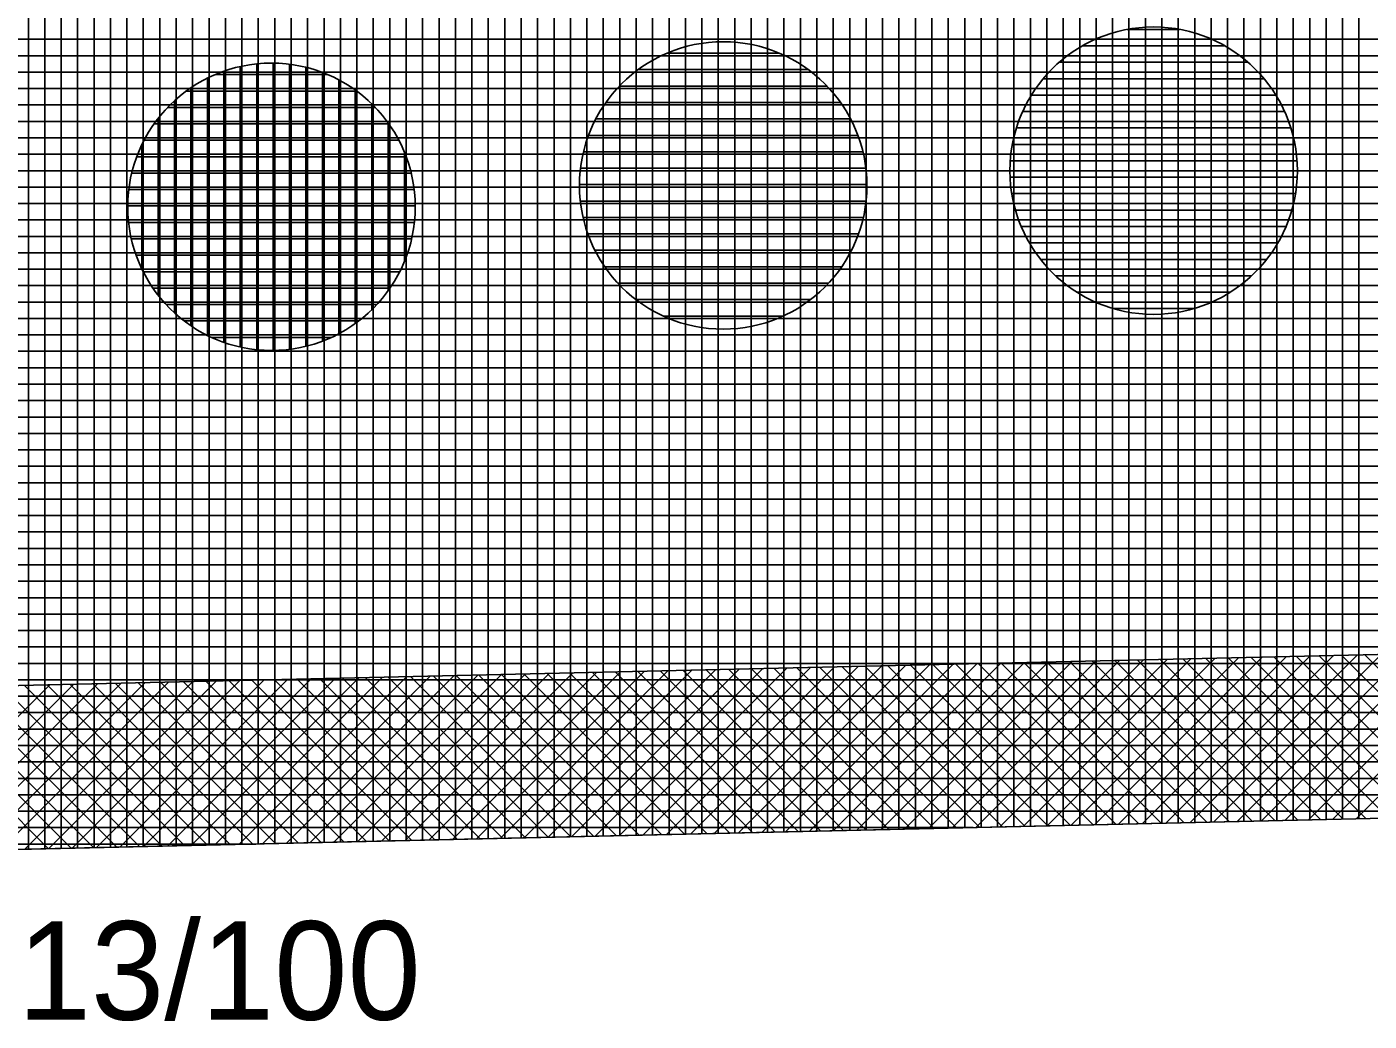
# Model space of a CAD drawing. Extents: x -565346 to -564154, y -1097386 to -1095620.
# Drawn here: x -565257.74 to -565241.4, y -1095873.9 to -1095861.79 of the extents above; entities that cross this region are included whole.
import ezdxf

# ---------------------------------------------------------------- set-up
doc = ezdxf.new("R2010")
doc.units = 0
for name, color, linetype in [('Vrstva 1', 7, 'Continuous'), ('Vrstva 40', 7, 'Continuous'), ('Vrstva 41', 7, 'Continuous'), ('Vrstva 42', 7, 'Continuous'), ('Vrstva 43', 7, 'Continuous'), ('Vrstva 44', 7, 'Continuous')]:
    doc.layers.add(name, color=color, linetype=linetype)

msp = doc.modelspace()

# ---------------------------------------------------------------- linework, layer by layer
at = {"layer": 'Vrstva 1'}
msp.add_line((-565318.28, -1095873.19), (-565230.93, -1095871.19), dxfattribs=at)
at = {"layer": 'Vrstva 41'}
for p, q in [((-565244.723, -1095869.512), (-565246.764, -1095871.553)), ((-565244.434, -1095869.505), (-565246.475, -1095871.546)), ((-565244.145, -1095869.498), (-565246.185, -1095871.539)), ((-565243.855, -1095869.492), (-565245.896, -1095871.533)), ((-565243.566, -1095869.485), (-565245.607, -1095871.526)), ((-565243.276, -1095869.479), (-565245.317, -1095871.519)), ((-565242.987, -1095869.472), (-565245.028, -1095871.513)), ((-565242.819, -1095871.462), (-565244.768, -1095869.513)), ((-565242.697, -1095869.465), (-565244.738, -1095871.506)), ((-565242.542, -1095871.456), (-565244.492, -1095869.506)), ((-565242.408, -1095869.459), (-565244.449, -1095871.5)), ((-565242.266, -1095871.45), (-565244.215, -1095869.5)), ((-565242.118, -1095869.452), (-565244.159, -1095871.493)), ((-565241.989, -1095871.443), (-565243.939, -1095869.494)), ((-565241.829, -1095869.446), (-565243.87, -1095871.486)), ((-565241.713, -1095871.437), (-565243.662, -1095869.487)), ((-565241.54, -1095869.439), (-565243.58, -1095871.48)), ((-565241.436, -1095871.431), (-565243.386, -1095869.481)), ((-565241.25, -1095869.432), (-565243.291, -1095871.473)), ((-565241.16, -1095871.424), (-565243.109, -1095869.475)), ((-565240.961, -1095869.426), (-565243.001, -1095871.466)), ((-565240.883, -1095871.418), (-565242.833, -1095869.469)), ((-565240.671, -1095869.419), (-565242.712, -1095871.46)), ((-565240.607, -1095871.412), (-565242.556, -1095869.462)), ((-565240.382, -1095869.413), (-565242.422, -1095871.453)), ((-565240.33, -1095871.405), (-565242.28, -1095869.456)), ((-565240.092, -1095869.406), (-565242.133, -1095871.447)), ((-565240.054, -1095871.399), (-565242.003, -1095869.45)), ((-565239.803, -1095869.399), (-565241.843, -1095871.44)), ((-565239.777, -1095871.393), (-565241.727, -1095869.443)), ((-565239.513, -1095869.393), (-565241.554, -1095871.433)), ((-565239.501, -1095871.386), (-565241.45, -1095869.437)), ((-565251.96, -1095869.677), (-565254.001, -1095871.718)), ((-565251.67, -1095869.67), (-565253.712, -1095871.712)), ((-565251.381, -1095869.664), (-565253.422, -1095871.705)), ((-565251.091, -1095869.657), (-565253.133, -1095871.698)), ((-565250.802, -1095869.65), (-565252.843, -1095871.692)), ((-565250.512, -1095869.644), (-565252.554, -1095871.685)), ((-565250.223, -1095869.637), (-565252.264, -1095871.678)), ((-565249.934, -1095869.631), (-565251.975, -1095871.672)), ((-565250.008, -1095871.627), (-565251.958, -1095869.677)), ((-565249.644, -1095869.624), (-565251.685, -1095871.665)), ((-565249.732, -1095871.62), (-565251.682, -1095869.67)), ((-565249.455, -1095871.614), (-565251.405, -1095869.664)), ((-565249.355, -1095869.617), (-565251.396, -1095871.659)), ((-565249.179, -1095871.608), (-565251.129, -1095869.658)), ((-565249.065, -1095869.611), (-565251.106, -1095871.652)), ((-565248.902, -1095871.601), (-565250.852, -1095869.651)), ((-565248.776, -1095869.604), (-565250.817, -1095871.645)), ((-565248.626, -1095871.595), (-565250.576, -1095869.645)), ((-565248.486, -1095869.598), (-565250.528, -1095871.639)), ((-565248.349, -1095871.589), (-565250.299, -1095869.639)), ((-565248.197, -1095869.591), (-565250.238, -1095871.632)), ((-565248.073, -1095871.583), (-565250.023, -1095869.633)), ((-565247.907, -1095869.584), (-565249.949, -1095871.625)), ((-565247.796, -1095871.576), (-565249.746, -1095869.626)), ((-565247.618, -1095869.578), (-565249.659, -1095871.619)), ((-565247.52, -1095871.57), (-565249.469, -1095869.62)), ((-565247.329, -1095869.571), (-565249.37, -1095871.612)), ((-565247.243, -1095871.564), (-565249.193, -1095869.614)), ((-565247.039, -1095869.564), (-565249.08, -1095871.606)), ((-565246.967, -1095871.557), (-565248.916, -1095869.607)), ((-565246.75, -1095869.558), (-565248.791, -1095871.599)), ((-565246.69, -1095871.551), (-565248.64, -1095869.601)), ((-565246.46, -1095869.551), (-565248.501, -1095871.592)), ((-565246.414, -1095871.545), (-565248.363, -1095869.595)), ((-565246.171, -1095869.545), (-565248.212, -1095871.586)), ((-565246.137, -1095871.538), (-565248.087, -1095869.588)), ((-565245.881, -1095869.538), (-565247.922, -1095871.579)), ((-565245.86, -1095871.532), (-565247.81, -1095869.582)), ((-565245.592, -1095869.531), (-565247.633, -1095871.572)), ((-565245.584, -1095871.526), (-565247.534, -1095869.576)), ((-565245.302, -1095869.525), (-565247.343, -1095871.566)), ((-565245.307, -1095871.519), (-565247.257, -1095869.569)), ((-565245.013, -1095869.518), (-565247.054, -1095871.559)), ((-565245.031, -1095871.513), (-565246.981, -1095869.563)), ((-565244.754, -1095871.507), (-565246.704, -1095869.557)), ((-565244.478, -1095871.5), (-565246.428, -1095869.551)), ((-565244.201, -1095871.494), (-565246.151, -1095869.544)), ((-565243.925, -1095871.488), (-565245.875, -1095869.538)), ((-565243.648, -1095871.481), (-565245.598, -1095869.532)), ((-565243.372, -1095871.475), (-565245.321, -1095869.525)), ((-565243.095, -1095871.469), (-565245.045, -1095869.519)), ((-565257.459, -1095869.802), (-565259.501, -1095871.844)), ((-565257.17, -1095869.796), (-565259.212, -1095871.838)), ((-565257.197, -1095871.791), (-565259.148, -1095869.841)), ((-565256.88, -1095869.789), (-565258.922, -1095871.831)), ((-565256.921, -1095871.785), (-565258.872, -1095869.834)), ((-565256.591, -1095869.782), (-565258.633, -1095871.824)), ((-565256.644, -1095871.779), (-565258.595, -1095869.828)), ((-565256.301, -1095869.776), (-565258.343, -1095871.818)), ((-565256.368, -1095871.772), (-565258.319, -1095869.822)), ((-565256.012, -1095869.769), (-565258.054, -1095871.811)), ((-565256.091, -1095871.766), (-565258.042, -1095869.816)), ((-565255.815, -1095871.76), (-565257.765, -1095869.809)), ((-565255.722, -1095869.763), (-565257.764, -1095871.804)), ((-565255.538, -1095871.753), (-565257.489, -1095869.803)), ((-565255.433, -1095869.756), (-565257.475, -1095871.798)), ((-565255.262, -1095871.747), (-565257.212, -1095869.797)), ((-565255.144, -1095869.749), (-565257.185, -1095871.791)), ((-565254.985, -1095871.741), (-565256.936, -1095869.79)), ((-565254.854, -1095869.743), (-565256.896, -1095871.785)), ((-565254.709, -1095871.734), (-565256.659, -1095869.784)), ((-565254.565, -1095869.736), (-565256.606, -1095871.778)), ((-565254.432, -1095871.728), (-565256.383, -1095869.778)), ((-565254.275, -1095869.73), (-565256.317, -1095871.771)), ((-565254.156, -1095871.722), (-565256.106, -1095869.771)), ((-565253.986, -1095869.723), (-565256.027, -1095871.765)), ((-565253.879, -1095871.715), (-565255.83, -1095869.765)), ((-565253.696, -1095869.716), (-565255.738, -1095871.758)), ((-565253.603, -1095871.709), (-565255.553, -1095869.759)), ((-565253.407, -1095869.71), (-565255.449, -1095871.751)), ((-565253.326, -1095871.703), (-565255.277, -1095869.752)), ((-565253.117, -1095869.703), (-565255.159, -1095871.745)), ((-565253.05, -1095871.696), (-565255, -1095869.746)), ((-565252.828, -1095869.697), (-565254.87, -1095871.738)), ((-565252.773, -1095871.69), (-565254.724, -1095869.74)), ((-565252.539, -1095869.69), (-565254.58, -1095871.732)), ((-565252.497, -1095871.684), (-565254.447, -1095869.734)), ((-565252.249, -1095869.683), (-565254.291, -1095871.725)), ((-565252.22, -1095871.677), (-565254.171, -1095869.727)), ((-565251.944, -1095871.671), (-565253.894, -1095869.721)), ((-565251.667, -1095871.665), (-565253.617, -1095869.715)), ((-565251.391, -1095871.658), (-565253.341, -1095869.708)), ((-565251.114, -1095871.652), (-565253.064, -1095869.702)), ((-565250.838, -1095871.646), (-565252.788, -1095869.696)), ((-565250.561, -1095871.639), (-565252.511, -1095869.689)), ((-565250.285, -1095871.633), (-565252.235, -1095869.683)), ((-565257.474, -1095871.798), (-565259.425, -1095869.847))]:
    msp.add_line(p, q, dxfattribs=at)
at = {"layer": 'Vrstva 42'}
msp.add_lwpolyline([(-565179.232, -1095865.407), (-565179.369, -1095863.41), (-565231.152, -1095869.202), (-565318.326, -1095871.191), (-565322.325, -1095871.281), (-565322.28, -1095873.28), (-565318.28, -1095873.19), (-565230.93, -1095871.19)], close=True, dxfattribs=at)
at = {"layer": 'Vrstva 43'}
for p, q in [((-565242.12, -1095856.439), (-565242.12, -1095871.446)), ((-565241.92, -1095856.435), (-565241.92, -1095871.442)), ((-565241.72, -1095856.43), (-565241.72, -1095871.437)), ((-565241.52, -1095856.425), (-565241.52, -1095871.432)), ((-565249.32, -1095856.605), (-565249.32, -1095871.611)), ((-565249.12, -1095856.6), (-565249.12, -1095871.606)), ((-565248.92, -1095856.595), (-565248.92, -1095871.602)), ((-565248.72, -1095856.591), (-565248.72, -1095871.597)), ((-565248.52, -1095856.586), (-565248.52, -1095871.593)), ((-565248.32, -1095856.582), (-565248.32, -1095871.588)), ((-565248.12, -1095856.577), (-565248.12, -1095871.584)), ((-565247.92, -1095856.572), (-565247.92, -1095871.579)), ((-565247.72, -1095856.568), (-565247.72, -1095871.574)), ((-565247.52, -1095856.563), (-565247.52, -1095871.57)), ((-565247.32, -1095856.559), (-565247.32, -1095871.565)), ((-565247.12, -1095856.554), (-565247.12, -1095871.561)), ((-565246.92, -1095856.549), (-565246.92, -1095871.556)), ((-565246.72, -1095856.545), (-565246.72, -1095871.552)), ((-565246.52, -1095856.54), (-565246.52, -1095871.547)), ((-565246.32, -1095856.536), (-565246.32, -1095871.542)), ((-565246.12, -1095856.531), (-565246.12, -1095871.538)), ((-565245.92, -1095856.526), (-565245.92, -1095871.533)), ((-565245.72, -1095856.522), (-565245.72, -1095871.529)), ((-565245.52, -1095856.517), (-565245.52, -1095871.524)), ((-565245.32, -1095856.513), (-565245.32, -1095871.519)), ((-565245.12, -1095856.508), (-565245.12, -1095871.515)), ((-565244.92, -1095856.503), (-565244.92, -1095871.51)), ((-565244.72, -1095856.499), (-565244.72, -1095871.506)), ((-565244.52, -1095856.494), (-565244.52, -1095871.501)), ((-565244.32, -1095856.49), (-565244.32, -1095871.497)), ((-565244.12, -1095856.485), (-565244.12, -1095871.492)), ((-565243.92, -1095856.481), (-565243.92, -1095871.487)), ((-565243.72, -1095856.476), (-565243.72, -1095871.483)), ((-565243.52, -1095856.471), (-565243.52, -1095871.478)), ((-565243.32, -1095856.467), (-565243.32, -1095871.474)), ((-565243.12, -1095856.462), (-565243.12, -1095871.469)), ((-565242.92, -1095856.458), (-565242.92, -1095871.465)), ((-565242.72, -1095856.453), (-565242.72, -1095871.46)), ((-565242.52, -1095856.448), (-565242.52, -1095871.455)), ((-565242.32, -1095856.444), (-565242.32, -1095871.451)), ((-565256.32, -1095856.765), (-565256.32, -1095871.771)), ((-565256.12, -1095856.761), (-565256.12, -1095871.767)), ((-565255.92, -1095856.756), (-565255.92, -1095871.762)), ((-565255.72, -1095856.752), (-565255.72, -1095871.758)), ((-565255.52, -1095856.747), (-565255.52, -1095871.753)), ((-565255.32, -1095856.742), (-565255.32, -1095871.748)), ((-565255.12, -1095856.738), (-565255.12, -1095871.744)), ((-565254.92, -1095856.733), (-565254.92, -1095871.739)), ((-565254.72, -1095856.729), (-565254.72, -1095871.735)), ((-565254.52, -1095856.724), (-565254.52, -1095871.73)), ((-565254.32, -1095856.719), (-565254.32, -1095871.726)), ((-565254.12, -1095856.715), (-565254.12, -1095871.721)), ((-565253.92, -1095856.71), (-565253.92, -1095871.716)), ((-565253.72, -1095856.706), (-565253.72, -1095871.712)), ((-565253.52, -1095856.701), (-565253.52, -1095871.707)), ((-565253.32, -1095856.696), (-565253.32, -1095871.703)), ((-565253.12, -1095856.692), (-565253.12, -1095871.698)), ((-565252.92, -1095856.687), (-565252.92, -1095871.693)), ((-565252.72, -1095856.683), (-565252.72, -1095871.689)), ((-565252.52, -1095856.678), (-565252.52, -1095871.684)), ((-565252.32, -1095856.673), (-565252.32, -1095871.68)), ((-565252.12, -1095856.669), (-565252.12, -1095871.675)), ((-565251.92, -1095856.664), (-565251.92, -1095871.671)), ((-565251.72, -1095856.66), (-565251.72, -1095871.666)), ((-565251.52, -1095856.655), (-565251.52, -1095871.661)), ((-565251.32, -1095856.65), (-565251.32, -1095871.657)), ((-565251.12, -1095856.646), (-565251.12, -1095871.652)), ((-565250.92, -1095856.641), (-565250.92, -1095871.648)), ((-565250.72, -1095856.637), (-565250.72, -1095871.643)), ((-565250.52, -1095856.632), (-565250.52, -1095871.639)), ((-565250.32, -1095856.628), (-565250.32, -1095871.634)), ((-565250.12, -1095856.623), (-565250.12, -1095871.629)), ((-565249.92, -1095856.618), (-565249.92, -1095871.625)), ((-565249.72, -1095856.614), (-565249.72, -1095871.62)), ((-565249.52, -1095856.609), (-565249.52, -1095871.616)), ((-565257.72, -1095856.797), (-565257.72, -1095871.803)), ((-565257.52, -1095856.793), (-565257.52, -1095871.799)), ((-565257.32, -1095856.788), (-565257.32, -1095871.794)), ((-565257.12, -1095856.784), (-565257.12, -1095871.79)), ((-565256.92, -1095856.779), (-565256.92, -1095871.785)), ((-565256.72, -1095856.775), (-565256.72, -1095871.78)), ((-565256.52, -1095856.77), (-565256.52, -1095871.776)), ((-565148.233, -1095861.94), (-565322.505, -1095861.94)), ((-565150.021, -1095862.14), (-565322.501, -1095862.14)), ((-565151.809, -1095862.34), (-565322.497, -1095862.34)), ((-565153.597, -1095862.54), (-565322.493, -1095862.54)), ((-565155.385, -1095862.74), (-565322.489, -1095862.74)), ((-565157.173, -1095862.94), (-565322.485, -1095862.94)), ((-565158.961, -1095863.14), (-565322.481, -1095863.14)), ((-565160.749, -1095863.34), (-565322.477, -1095863.34)), ((-565162.537, -1095863.54), (-565322.473, -1095863.54)), ((-565164.325, -1095863.74), (-565322.469, -1095863.74)), ((-565166.113, -1095863.94), (-565322.465, -1095863.94)), ((-565167.901, -1095864.14), (-565322.461, -1095864.14)), ((-565169.689, -1095864.34), (-565322.457, -1095864.34)), ((-565171.477, -1095864.54), (-565322.453, -1095864.54)), ((-565173.265, -1095864.74), (-565322.449, -1095864.74)), ((-565175.053, -1095864.94), (-565322.445, -1095864.94)), ((-565176.841, -1095865.14), (-565322.441, -1095865.14)), ((-565178.629, -1095865.34), (-565322.437, -1095865.34)), ((-565180.418, -1095865.54), (-565322.433, -1095865.54)), ((-565182.206, -1095865.74), (-565322.429, -1095865.74)), ((-565183.994, -1095865.94), (-565322.426, -1095865.94)), ((-565185.782, -1095866.14), (-565322.422, -1095866.14)), ((-565187.57, -1095866.34), (-565322.418, -1095866.34)), ((-565189.358, -1095866.54), (-565322.414, -1095866.54)), ((-565191.146, -1095866.74), (-565322.41, -1095866.74)), ((-565192.934, -1095866.94), (-565322.406, -1095866.94)), ((-565194.722, -1095867.14), (-565322.402, -1095867.14)), ((-565196.51, -1095867.34), (-565322.398, -1095867.34)), ((-565198.298, -1095867.54), (-565322.394, -1095867.54)), ((-565200.086, -1095867.74), (-565322.39, -1095867.74)), ((-565201.874, -1095867.94), (-565322.386, -1095867.94)), ((-565203.662, -1095868.14), (-565322.382, -1095868.14)), ((-565205.45, -1095868.34), (-565322.378, -1095868.34)), ((-565207.238, -1095868.54), (-565322.374, -1095868.54)), ((-565209.026, -1095868.74), (-565322.37, -1095868.74)), ((-565210.814, -1095868.94), (-565322.366, -1095868.94)), ((-565212.602, -1095869.14), (-565322.362, -1095869.14)), ((-565214.391, -1095869.34), (-565322.358, -1095869.34)), ((-565216.179, -1095869.54), (-565322.354, -1095869.54)), ((-565217.967, -1095869.74), (-565322.35, -1095869.74)), ((-565219.755, -1095869.94), (-565322.346, -1095869.94)), ((-565221.543, -1095870.14), (-565322.342, -1095870.14)), ((-565223.331, -1095870.34), (-565322.338, -1095870.34)), ((-565225.119, -1095870.54), (-565322.334, -1095870.54)), ((-565226.907, -1095870.74), (-565322.33, -1095870.74)), ((-565228.695, -1095870.94), (-565322.326, -1095870.94)), ((-565230.483, -1095871.14), (-565322.322, -1095871.14)), ((-565237.481, -1095871.34), (-565322.318, -1095871.34)), ((-565246.216, -1095871.54), (-565322.314, -1095871.54)), ((-565254.951, -1095871.74), (-565322.311, -1095871.74))]:
    msp.add_line(p, q, dxfattribs=at)
msp.add_lwpolyline([(-565311.82, -1095858.04), (-565322.62, -1095856.13), (-565322.28, -1095873.28), (-565318.28, -1095873.19), (-565230.93, -1095871.19), (-565052.84, -1095851.27), (-565052.77, -1095836.13), (-565130.42, -1095846.37), (-565188.3, -1095850.34), (-565231.27, -1095856.19)], close=True, dxfattribs=at)
at = {"layer": 'Vrstva 44'}
for p, q in [((-565244.34, -1095861.82), (-565243.706, -1095861.82)), ((-565244.32, -1095861.816), (-565244.32, -1095865.262)), ((-565244.12, -1095861.794), (-565244.12, -1095865.285)), ((-565243.92, -1095861.795), (-565243.92, -1095865.286)), ((-565243.72, -1095861.818), (-565243.72, -1095865.263)), ((-565249.52, -1095861.991), (-565249.52, -1095865.449)), ((-565249.32, -1095861.973), (-565249.32, -1095865.468)), ((-565249.12, -1095861.977), (-565249.12, -1095865.463)), ((-565244.72, -1095861.938), (-565244.72, -1095865.142)), ((-565244.52, -1095861.864), (-565244.52, -1095865.217)), ((-565243.52, -1095861.864), (-565243.52, -1095865.215)), ((-565243.32, -1095861.937), (-565243.32, -1095865.142)), ((-565249.941, -1095862.11), (-565248.575, -1095862.11)), ((-565249.92, -1095862.101), (-565249.92, -1095865.34)), ((-565249.72, -1095862.032), (-565249.72, -1095865.408)), ((-565248.92, -1095862.004), (-565248.92, -1095865.435)), ((-565248.72, -1095862.056), (-565248.72, -1095865.383)), ((-565248.52, -1095862.136), (-565248.52, -1095865.305)), ((-565244.92, -1095862.041), (-565244.92, -1095865.039)), ((-565244.883, -1095862.02), (-565243.156, -1095862.02)), ((-565243.12, -1095862.041), (-565243.12, -1095865.04)), ((-565255.14, -1095862.274), (-565255.14, -1095865.688)), ((-565254.94, -1095862.241), (-565254.94, -1095865.719)), ((-565254.74, -1095862.23), (-565254.74, -1095865.728)), ((-565254.54, -1095862.245), (-565254.54, -1095865.714)), ((-565254.34, -1095862.283), (-565254.34, -1095865.678)), ((-565250.294, -1095862.31), (-565248.227, -1095862.31)), ((-565250.12, -1095862.198), (-565250.12, -1095865.242)), ((-565248.32, -1095862.245), (-565248.32, -1095865.194)), ((-565245.166, -1095862.22), (-565242.874, -1095862.22)), ((-565245.12, -1095862.181), (-565245.12, -1095864.9)), ((-565242.92, -1095862.179), (-565242.92, -1095864.899)), ((-565255.54, -1095862.414), (-565255.54, -1095865.545)), ((-565255.441, -1095862.37), (-565254.075, -1095862.37)), ((-565255.34, -1095862.331), (-565255.34, -1095865.629)), ((-565254.14, -1095862.345), (-565254.14, -1095865.616)), ((-565253.94, -1095862.434), (-565253.94, -1095865.524)), ((-565250.32, -1095862.328), (-565250.32, -1095865.111)), ((-565248.12, -1095862.394), (-565248.12, -1095865.046)), ((-565245.362, -1095862.42), (-565242.676, -1095862.42)), ((-565245.32, -1095862.369), (-565245.32, -1095864.709)), ((-565242.72, -1095862.371), (-565242.72, -1095864.711)), ((-565255.794, -1095862.57), (-565253.727, -1095862.57)), ((-565255.74, -1095862.532), (-565255.74, -1095865.428)), ((-565253.74, -1095862.56), (-565253.74, -1095865.4)), ((-565250.522, -1095862.51), (-565247.998, -1095862.51)), ((-565250.52, -1095862.508), (-565250.52, -1095864.932)), ((-565247.92, -1095862.595), (-565247.92, -1095864.843)), ((-565245.52, -1095862.64), (-565245.52, -1095864.439)), ((-565245.507, -1095862.62), (-565242.534, -1095862.62)), ((-565242.52, -1095862.642), (-565242.52, -1095864.44)), ((-565256.022, -1095862.77), (-565253.498, -1095862.77)), ((-565255.94, -1095862.689), (-565255.94, -1095865.27)), ((-565253.54, -1095862.726), (-565253.54, -1095865.232)), ((-565250.72, -1095862.759), (-565250.72, -1095864.682)), ((-565250.688, -1095862.71), (-565247.832, -1095862.71)), ((-565256.188, -1095862.97), (-565253.332, -1095862.97)), ((-565256.14, -1095862.907), (-565256.14, -1095865.053)), ((-565253.34, -1095862.96), (-565253.34, -1095865.001)), ((-565250.809, -1095862.91), (-565247.71, -1095862.91)), ((-565247.72, -1095862.89), (-565247.72, -1095864.547)), ((-565245.614, -1095862.82), (-565242.426, -1095862.82)), ((-565250.899, -1095863.11), (-565247.622, -1095863.11)), ((-565245.72, -1095863.127), (-565245.72, -1095863.953)), ((-565245.689, -1095863.02), (-565242.35, -1095863.02)), ((-565242.32, -1095863.13), (-565242.32, -1095863.949)), ((-565256.34, -1095863.229), (-565256.34, -1095864.729)), ((-565256.309, -1095863.17), (-565253.21, -1095863.17)), ((-565250.92, -1095863.171), (-565250.92, -1095864.272)), ((-565245.739, -1095863.22), (-565242.301, -1095863.22)), ((-565256.399, -1095863.37), (-565253.122, -1095863.37)), ((-565253.14, -1095863.322), (-565253.14, -1095864.637)), ((-565250.961, -1095863.31), (-565247.56, -1095863.31)), ((-565245.765, -1095863.42), (-565242.276, -1095863.42)), ((-565256.461, -1095863.57), (-565253.06, -1095863.57)), ((-565250.996, -1095863.51), (-565247.523, -1095863.51)), ((-565247.52, -1095863.548), (-565247.52, -1095863.89)), ((-565245.768, -1095863.62), (-565242.273, -1095863.62)), ((-565256.496, -1095863.77), (-565253.023, -1095863.77)), ((-565251.008, -1095863.71), (-565247.511, -1095863.71)), ((-565250.998, -1095863.91), (-565247.522, -1095863.91)), ((-565245.746, -1095863.82), (-565242.293, -1095863.82)), ((-565256.508, -1095863.97), (-565253.011, -1095863.97)), ((-565250.965, -1095864.11), (-565247.556, -1095864.11)), ((-565245.701, -1095864.02), (-565242.338, -1095864.02)), ((-565256.498, -1095864.17), (-565253.022, -1095864.17)), ((-565245.631, -1095864.22), (-565242.41, -1095864.22)), ((-565256.465, -1095864.37), (-565253.056, -1095864.37)), ((-565250.906, -1095864.31), (-565247.613, -1095864.31)), ((-565245.532, -1095864.42), (-565242.509, -1095864.42)), ((-565256.406, -1095864.57), (-565253.113, -1095864.57)), ((-565250.819, -1095864.51), (-565247.7, -1095864.51)), ((-565256.319, -1095864.77), (-565253.2, -1095864.77)), ((-565250.702, -1095864.71), (-565247.819, -1095864.71)), ((-565245.394, -1095864.62), (-565242.645, -1095864.62)), ((-565250.54, -1095864.91), (-565247.978, -1095864.91)), ((-565245.212, -1095864.82), (-565242.828, -1095864.82)), ((-565256.202, -1095864.97), (-565253.319, -1095864.97)), ((-565244.952, -1095865.02), (-565243.088, -1095865.02)), ((-565256.04, -1095865.17), (-565253.478, -1095865.17)), ((-565250.321, -1095865.11), (-565248.198, -1095865.11)), ((-565244.509, -1095865.22), (-565243.535, -1095865.22)), ((-565255.821, -1095865.37), (-565253.698, -1095865.37)), ((-565249.986, -1095865.31), (-565248.532, -1095865.31)), ((-565255.486, -1095865.57), (-565254.032, -1095865.57))]:
    msp.add_line(p, q, dxfattribs=at)
for centre in [(-565244.02, -1095863.54), (-565249.26, -1095863.72), (-565254.76, -1095863.98)]:
    msp.add_circle(centre, 1.75, dxfattribs=at)

# ---------------------------------------------------------------- texts
at = {"layer": 'Vrstva 40'}
msp.add_text('13/100', height=1.2, dxfattribs=at).set_placement((-565257.85, -1095873.88))

doc.saveas('drawing.dxf')
